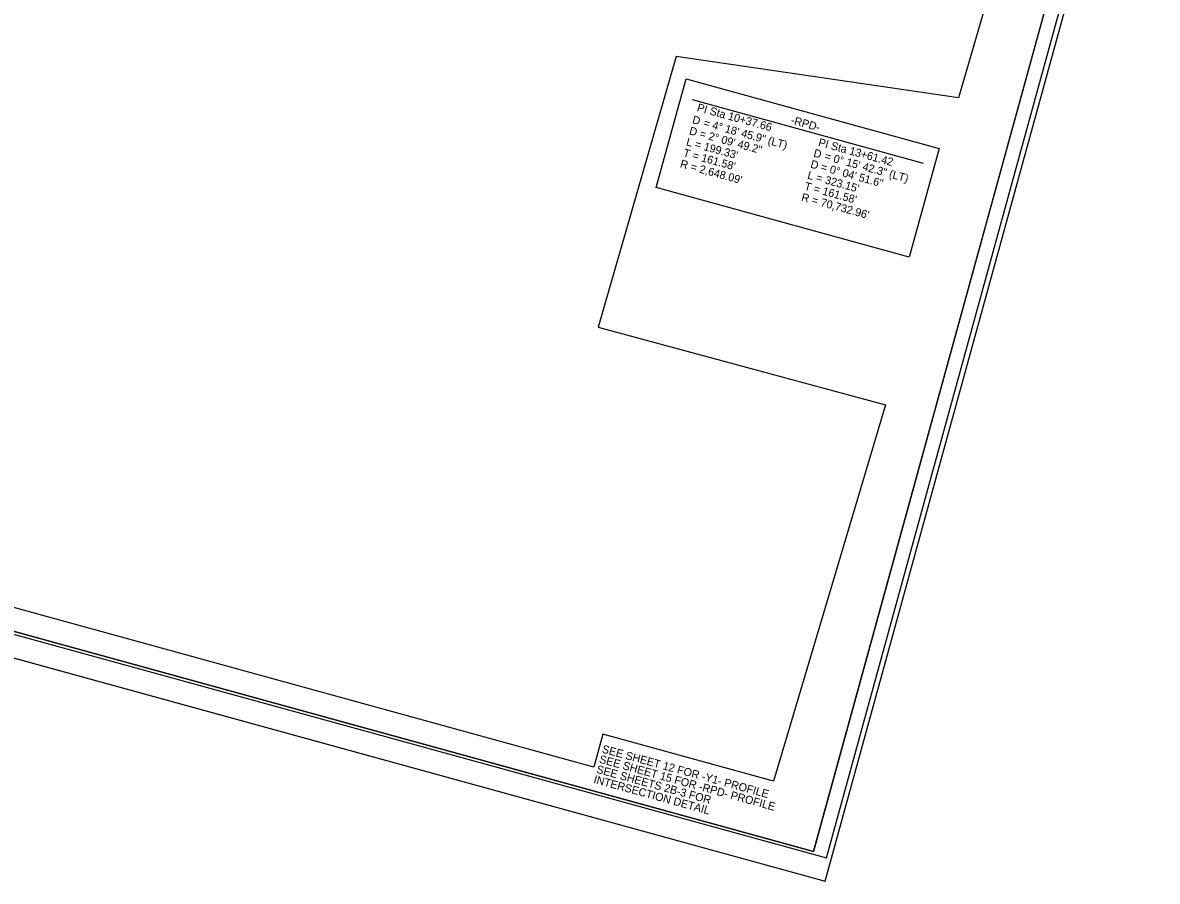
# Model space of a CAD drawing. Extents: x 1641063 to 2864602, y 841295 to 973236.
# Drawn here: x 1642113 to 1643106, y 841295 to 842047 of the extents above; entities that cross this region are included whole.
import ezdxf

# ---------------------------------------------------------------- set-up
doc = ezdxf.new("R2010")
doc.units = 0
for name, color, linetype in [('Exist CMT Alignment Centerline', 7, 'Continuous'), ('Old_Level_4', 7, 'Continuous'), ('Prop CMT Concrete Structures', 7, 'Continuous'), ('Prop CMT Pvmt Surface', 7, 'Continuous'), ('Prop Dimension Text', 7, 'Continuous'), ('Prop PHM Wetland Impact Area Boundary Line', 7, 'Continuous'), ('Prop Superelevation Label', 7, 'Continuous')]:
    doc.layers.add(name, color=color, linetype=linetype)

msp = doc.modelspace()

# ---------------------------------------------------------------- linework, layer by layer
at = {"layer": 'Old_Level_4'}
msp.add_lwpolyline([(1641192.11, 841741.99), (1642815.27, 841295.31), (1643105.8, 842351.06), (1641482.64, 842797.74)], close=True, dxfattribs=at)
msp.add_lwpolyline([(1641192.11, 841741.99), (1642815.27, 841295.31), (1643105.8, 842351.06), (1641482.64, 842797.74)], close=True, dxfattribs=at)
at = {"layer": 'Prop CMT Concrete Structures'}
for points in [[(1643083.47, 842333.88), (1641637.2, 842731.89), (1641358.6, 841719.52), (1642804.85, 841321.52)], [(1641358.6, 841719.52), (1641637.16, 842731.87), (1642890.57, 842386.98), (1642850.76, 842242.29), (1643043.63, 842189.2), (1642804.85, 841321.52)]]:
    msp.add_lwpolyline(points, close=True, dxfattribs=at)
at = {"layer": 'Prop CMT Pvmt Surface'}
msp.add_line((1642698.89, 841979.32), (1642901, 841923.7), dxfattribs=at)
msp.add_lwpolyline([(1642693.49, 841997.4), (1642914.88, 841936.47), (1642888.7, 841841.33), (1642667.31, 841902.25)], close=True, dxfattribs=at)
at = {"layer": 'Prop Dimension Text'}
msp.add_lwpolyline([(1641209.95, 841757.82), (1642816.23, 841315.8), (1643096.16, 842332.97), (1641489.87, 842775.01)], close=True, dxfattribs=at)
at = {"layer": 'Prop PHM Wetland Impact Area Boundary Line'}
msp.add_lwpolyline([(1642834.84, 842332.26), (1642796.64, 842193.46), (1642979.12, 842143.25), (1642931.91, 841980.78), (1642684.68, 842016.94), (1642616.55, 841780.17), (1642867.94, 841712.2), (1642769.91, 841383), (1642620.74, 841424.05), (1642612.78, 841395.12), (1641412.11, 841725.54), (1641476.31, 841958.82), (1641627.07, 841958.82), (1641755.49, 842119.21), (1641752.38, 842181.83), (1641796.56, 842667.29)], dxfattribs=at)
at = {"layer": 'Prop Superelevation Label'}
msp.add_line((1641192.11, 841741.99), (1642815.27, 841295.31), dxfattribs=at)

# ---------------------------------------------------------------- texts
at = {"layer": 'Exist CMT Alignment Centerline'}
for s, p in [('SEE SHEET 12 FOR -Y1- PROFILE', (1642619.37, 841408.06)), ('SEE SHEET 15 FOR -RPD- PROFILE', (1642616.94, 841399.21)), ('SEE SHEETS 2B-3 FOR', (1642614.5, 841390.36)), ('INTERSECTION DETAIL', (1642612.07, 841381.51))]:
    msp.add_text(s, height=7, rotation=344.6135, dxfattribs=at).set_placement(p)
at = {"layer": 'Prop CMT Pvmt Surface'}
for s, p in [('PI Sta 10+37.66', (1642702.55, 841969.31)), ('D ', (1642698.4, 841958.71)), ('= 4%%d 18\' 45.9" (LT)', (1642708.02, 841955.98)), ('-RPD-', (1642784.6, 841958.32)), ('D = 2%%d 09\' 49.2"', (1642695.73, 841948.99)), ("L = 199.33'", (1642693.08, 841939.35)), ('PI Sta 13+61.42', (1642808.64, 841938.87)), ("T = 161.58'", (1642690.42, 841929.71)), ('D ', (1642804.46, 841929.52)), ('= 0%%d 15\' 42.3" (LT)', (1642814.08, 841926.8)), ("R = 2,648.09'", (1642687.77, 841920.07)), ('D = 0%%d 04\' 51.6"', (1642801.79, 841919.81)), ("L = 323.15'", (1642799.13, 841910.17)), ("T = 161.58'", (1642796.48, 841900.53)), ("R = 70,732.96'", (1642793.83, 841890.88))]:
    msp.add_text(s, height=7, rotation=344.6135, dxfattribs=at).set_placement(p)

doc.saveas('drawing.dxf')
